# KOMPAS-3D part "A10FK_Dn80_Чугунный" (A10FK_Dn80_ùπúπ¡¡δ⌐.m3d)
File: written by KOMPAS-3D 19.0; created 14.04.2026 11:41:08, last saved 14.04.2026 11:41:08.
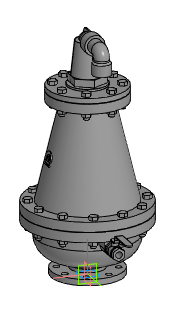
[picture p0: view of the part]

Document properties: Автор: Энергия; Полное имя файла: Z:\3.Личные\kachalov\3d для проектировщиков\x.x Тип A10FK Двухступенчатый воздухоотводчик\stp_Тип A10FK Двухступенчатый воздухоотводчик\A10FK_Dn80_Чугунный.m3d

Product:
- Part/product: A10FK_Dn80_Чугунный

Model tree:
1. Операция без истории:1  (labels: A10FK_Dn80_Чугунный)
